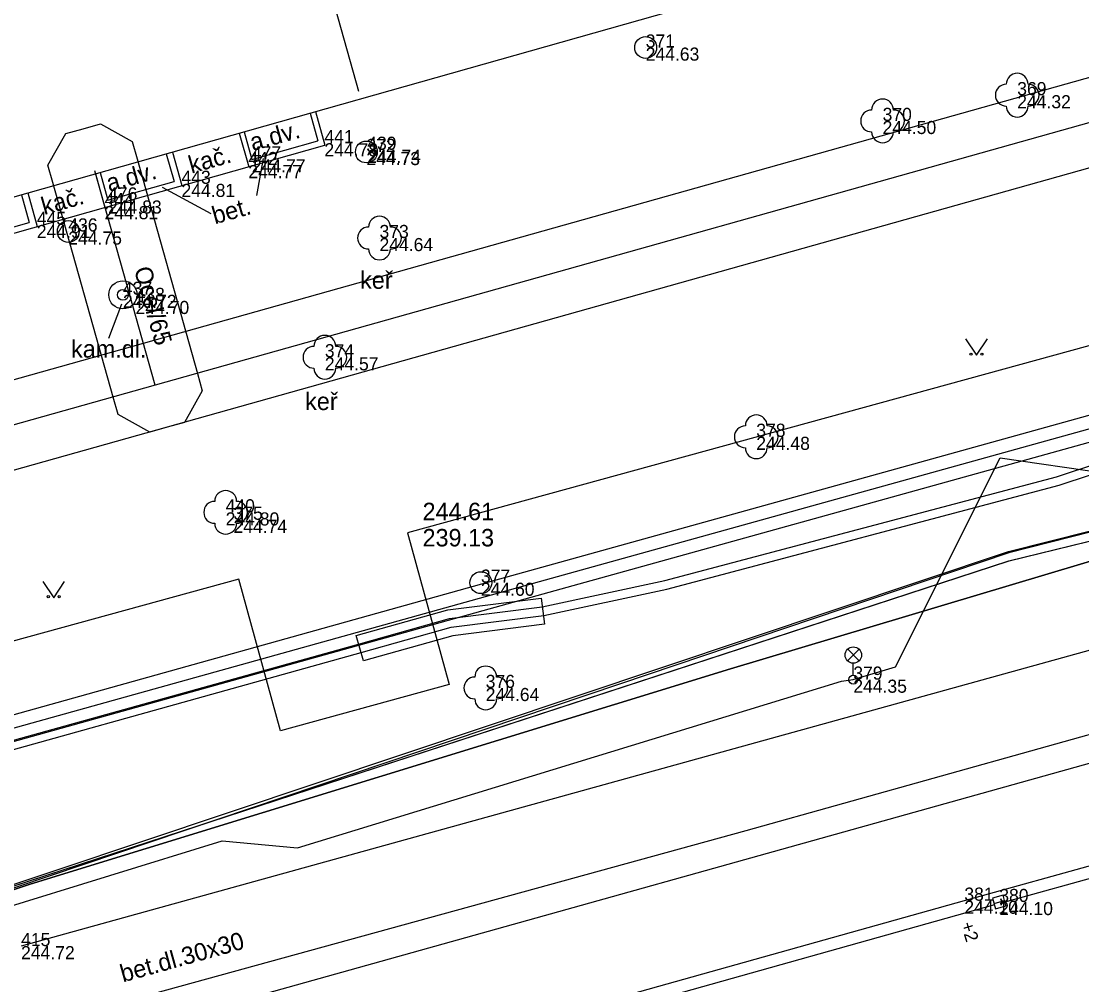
# Model space of a CAD drawing. Extents: x -599432 to -598680, y -1159407 to -1158632.
# Drawn here: x -599169.23 to -599144.96, y -1158932.91 to -1158910.85 of the extents above; entities that cross this region are included whole.
import ezdxf

# ---------------------------------------------------------------- set-up
doc = ezdxf.new("R2010")
doc.units = 0
for name, color, linetype in [('0004 VY - Body podrobné', 7, 'Continuous'), ('0005 VY - Body podrobné - čísla', 7, 'Continuous'), ('0006 VY - Body podrobné - výšky', 7, 'Continuous'), ('0007 ZA - Budova - zděná', 7, 'Continuous'), ('0027 ZA - Silnice_cesta zpevněná', 7, 'Continuous'), ('0028 ZA - Silnice - nájezd na chodník', 7, 'Continuous'), ('0030 ZA - Chodník', 7, 'Continuous'), ('0031 ZA - Ostatní rozhraní', 7, 'Continuous'), ('0032 TE - Popis povrchu', 7, 'Continuous'), ('0034 ZA - Kultury - značky', 7, 'Continuous'), ('0035 ZA - Strom - značka', 7, 'Continuous'), ('0036 TE - Strom - popis', 7, 'Continuous'), ('0073 TE - Výška obrubníků a zdí', 7, 'Continuous'), ('0075 ZA - BVK - kanalizace - buňky', 7, 'Continuous'), ('0092 ZA - RWE - plynovod - buňky', 7, 'Continuous'), ('0105 ZA - TSB - VO - buňky', 7, 'Continuous'), ('0116 PV - budova převzatá z mapy', 7, 'Continuous'), ('0201 PV - BVK - kanalizace - popis', 7, 'Continuous'), ('0202 PV - MUNI', 7, 'Continuous'), ('0206 PV - BVK - kanalizace - jednotná', 7, 'Continuous'), ('0211 PV - BVK - kanalizace - jednotná okraj', 7, 'Continuous'), ('0264 PV - TB - parovod mimo provoz', 7, 'Continuous'), ('0301 PV - RWE - popis', 7, 'Continuous'), ('0302 PV - RWE - NTL', 7, 'Continuous'), ('0303 PV - RWE - NTL přípojka', 7, 'Continuous'), ('0308 PV - RWE - ochranné pásmo', 7, 'Continuous'), ('0354 PV - EON - VN', 7, 'Continuous'), ('0359 PV - EON - sdělovací kabely', 7, 'Continuous'), ('0367 PV - EON - VN chránička', 7, 'Continuous'), ('0407 PV - TSB - kabelové vedení přibližný zákres', 7, 'Continuous'), ('0454 PV - O2 - kabel zaměřený', 7, 'Continuous'), ('0530 PV - T-mobile - optické kabely', 7, 'Continuous'), ('0652 PV - BKOM - kabely bez rozlišení', 7, 'Continuous'), ('0703 PV - DIAL TELECOM optický kabel', 7, 'Continuous'), ('0704 PV - ČD - kabely', 7, 'Continuous')]:
    doc.layers.add(name, color=color, linetype=linetype)

msp = doc.modelspace()

# ---------------------------------------------------------------- linework, layer by layer
at = {"layer": '0004 VY - Body podrobné'}
for p, q in [((-599154.94, -1158911.45), (-599154.94, -1158911.45)), ((-599146.44, -1158912.54), (-599146.44, -1158912.54)), ((-599149.52, -1158913.13), (-599149.52, -1158913.13)), ((-599162.29, -1158913.64), (-599162.29, -1158913.64)), ((-599163.95, -1158914.01), (-599163.95, -1158914.01)), ((-599161.33, -1158913.84), (-599161.33, -1158913.84)), ((-599161.31, -1158913.79), (-599161.31, -1158913.79)), ((-599164.03, -1158914.14), (-599164.03, -1158914.14)), ((-599165.56, -1158914.57), (-599165.56, -1158914.57)), ((-599167.24, -1158914.95), (-599167.24, -1158914.95)), ((-599167.32, -1158915.08), (-599167.32, -1158915.08)), ((-599168.87, -1158915.51), (-599168.87, -1158915.51)), ((-599168.15, -1158915.66), (-599168.15, -1158915.66)), ((-599161.03, -1158915.81), (-599161.03, -1158915.81)), ((-599166.9, -1158917.11), (-599166.9, -1158917.11)), ((-599166.61, -1158917.25), (-599166.61, -1158917.25)), ((-599162.28, -1158918.54), (-599162.28, -1158918.54)), ((-599152.41, -1158920.36), (-599152.41, -1158920.36)), ((-599164.55, -1158922.09), (-599164.55, -1158922.09)), ((-599164.37, -1158922.26), (-599164.37, -1158922.26)), ((-599158.71, -1158923.7), (-599158.71, -1158923.7)), ((-599158.6, -1158926.11), (-599158.6, -1158926.11)), ((-599150.19, -1158925.92), (-599150.19, -1158925.92)), ((-599147.65, -1158930.98), (-599147.65, -1158930.98)), ((-599146.85, -1158931.01), (-599146.85, -1158931.01))]:
    msp.add_line(p, q, dxfattribs=at)
at = {"layer": '0007 ZA - Budova - zděná'}
msp.add_line((-599202.3, -1158924.18), (-599142.02, -1158907.12), dxfattribs=at)
at = {"layer": '0027 ZA - Silnice_cesta zpevněná'}
msp.add_line((-599137.26, -1158925.73), (-599166.94, -1158934.03), dxfattribs=at)
at = {"layer": '0028 ZA - Silnice - nájezd na chodník'}
for p, q in [((-599088.5, -1158914.55), (-599147.65, -1158930.98)), ((-599147.65, -1158930.98), (-599167.27, -1158936.48))]:
    msp.add_line(p, q, dxfattribs=at)
at = {"layer": '0030 ZA - Chodník'}
msp.add_line((-599144.32, -1158925.12), (-599169.23, -1158932.02), dxfattribs=at)
at = {"layer": '0031 ZA - Ostatní rozhraní'}
for p, q in [((-599162.618, -1158912.95), (-599162.439, -1158913.585)), ((-599162.495, -1158912.915), (-599162.277, -1158913.685)), ((-599164.237, -1158913.408), (-599164.019, -1158914.178)), ((-599164.129, -1158913.377), (-599163.949, -1158914.012)), ((-599180.694, -1158918.897), (-599162.277, -1158913.685)), ((-599163.949, -1158914.012), (-599162.439, -1158913.585)), ((-599165.911, -1158913.881), (-599165.731, -1158914.516)), ((-599165.766, -1158913.841), (-599165.549, -1158914.61)), ((-599167.53, -1158914.34), (-599167.312, -1158915.109)), ((-599167.421, -1158914.309), (-599167.242, -1158914.944)), ((-599167.242, -1158914.944), (-599165.731, -1158914.516)), ((-599169.224, -1158914.819), (-599169.045, -1158915.454)), ((-599169.077, -1158914.778), (-599168.859, -1158915.547)), ((-599088.425, -1158914.82), (-599146.72, -1158931.012)), ((-599170.555, -1158915.882), (-599169.045, -1158915.454)), ((-599146.961, -1158931.078), (-599167.194, -1158936.75))]:
    msp.add_line(p, q, dxfattribs=at)
msp.add_circle((-599166.9, -1158917.11), 0.322, dxfattribs=at)
at = {"layer": '0032 TE - Popis povrchu'}
for p, q in [((-599163.835, -1158914.838), (-599163.682, -1158913.99)), ((-599164.884, -1158915.257), (-599165.997, -1158914.652)), ((-599167.223, -1158918.104), (-599166.928, -1158917.317))]:
    msp.add_line(p, q, dxfattribs=at)
at = {"layer": '0034 ZA - Kultury - značky'}
for points in [[(-599147.623, -1158918.118), (-599147.373, -1158918.493), (-599147.123, -1158918.118)], [(-599168.733, -1158923.67), (-599168.483, -1158924.045), (-599168.233, -1158923.67)]]:
    msp.add_lwpolyline(points, dxfattribs=at)
for centre in [(-599147.498, -1158918.468), (-599147.248, -1158918.468), (-599168.608, -1158924.02), (-599168.358, -1158924.02)]:
    msp.add_circle(centre, 0.025, dxfattribs=at)
at = {"layer": '0035 ZA - Strom - značka'}
for centre in [(-599146.44, -1158912.54), (-599149.52, -1158913.13), (-599161.03, -1158915.81), (-599162.28, -1158918.54), (-599152.41, -1158920.36), (-599164.55, -1158922.09), (-599158.6, -1158926.11)]:
    msp.add_circle(centre, 0.00025, dxfattribs=at)
for centre, start, end in [((-599146.44, -1158912.29), 0, 180), ((-599146.69, -1158912.54), 90, 270), ((-599146.19, -1158912.54), 270, 90), ((-599149.52, -1158912.88), 0, 180), ((-599146.44, -1158912.79), 180, 360), ((-599149.77, -1158913.13), 90, 270), ((-599149.27, -1158913.13), 270, 90), ((-599149.52, -1158913.38), 180, 360), ((-599161.03, -1158915.56), 0, 180), ((-599161.28, -1158915.81), 90, 270), ((-599160.78, -1158915.81), 270, 90), ((-599161.03, -1158916.06), 180, 360), ((-599162.28, -1158918.29), 0, 180), ((-599162.53, -1158918.54), 90, 270), ((-599162.03, -1158918.54), 270, 90), ((-599162.28, -1158918.79), 180, 360), ((-599152.41, -1158920.11), 0, 180), ((-599152.66, -1158920.36), 90, 270), ((-599152.16, -1158920.36), 270, 90), ((-599152.41, -1158920.61), 180, 360), ((-599164.55, -1158921.84), 0, 180), ((-599164.8, -1158922.09), 90, 270), ((-599164.3, -1158922.09), 270, 90), ((-599164.55, -1158922.34), 180, 360), ((-599158.6, -1158925.86), 0, 180), ((-599158.85, -1158926.11), 90, 270), ((-599158.35, -1158926.11), 270, 90), ((-599158.6, -1158926.36), 180, 360)]:
    msp.add_arc(centre, 0.25, start, end, dxfattribs=at)
at = {"layer": '0075 ZA - BVK - kanalizace - buňky'}
msp.add_line((-599146.971, -1158931.043), (-599146.729, -1158930.977), dxfattribs=at)
msp.add_lwpolyline([(-599146.938, -1158931.163), (-599146.697, -1158931.098), (-599146.762, -1158930.857), (-599147.003, -1158930.922)], close=True, dxfattribs=at)
for centre in [(-599154.94, -1158911.45), (-599161.33, -1158913.84), (-599168.15, -1158915.66), (-599158.71, -1158923.7)]:
    msp.add_circle(centre, 0.25, dxfattribs=at)
at = {"layer": '0092 ZA - RWE - plynovod - buňky'}
msp.add_circle((-599166.9, -1158917.11), 0.125, dxfattribs=at)
at = {"layer": '0105 ZA - TSB - VO - buňky'}
for p, q in [((-599150.322, -1158925.489), (-599150.058, -1158925.225)), ((-599150.054, -1158925.488), (-599150.318, -1158925.223)), ((-599150.19, -1158925.82), (-599150.19, -1158925.545))]:
    msp.add_line(p, q, dxfattribs=at)
for centre, radius in [((-599150.19, -1158925.357), 0.188), ((-599150.19, -1158925.92), 0.1)]:
    msp.add_circle(centre, radius, dxfattribs=at)
at = {"layer": '0116 PV - budova převzatá z mapy'}
msp.add_line((-599165.24, -1158899.13), (-599161.51, -1158912.45), dxfattribs=at)
at = {"layer": '0202 PV - MUNI'}
msp.add_lwpolyline([(-599255.365, -1158936.128), (-599252.9, -1158935.879), (-599249.514, -1158936.12), (-599229.166, -1158928.515), (-599221.329, -1158925.93), (-599220.289, -1158926.362), (-599218.079, -1158932.75), (-599214.197, -1158932.926), (-599209.818, -1158931.805), (-599201.617, -1158928.611), (-599200.477, -1158928.983), (-599199.188, -1158931.945), (-599199.148, -1158932.658), (-599198.604, -1158933.738), (-599197.027, -1158935.771), (-599194.361, -1158937.172), (-599193.665, -1158937.164), (-599183.138, -1158934.154), (-599174.357, -1158932.265), (-599146.637, -1158922.988), (-599125.848, -1158917.745)], dxfattribs=at)
at = {"layer": '0206 PV - BVK - kanalizace - jednotná'}
for p, q in [((-599158.607, -1158924.017), (-599091.321, -1158905.303)), ((-599214.704, -1158939.667), (-599158.607, -1158924.017))]:
    msp.add_line(p, q, dxfattribs=at)
at = {"layer": '0211 PV - BVK - kanalizace - jednotná okraj'}
for p, q in [((-599158.687, -1158923.728), (-599091.402, -1158905.014)), ((-599091.241, -1158905.592), (-599158.526, -1158924.307)), ((-599214.784, -1158939.378), (-599158.687, -1158923.729)), ((-599158.526, -1158924.306), (-599214.623, -1158939.956))]:
    msp.add_line(p, q, dxfattribs=at)
at = {"layer": '0264 PV - TB - parovod mimo provoz'}
msp.add_line((-599074.078, -1158898.846), (-599160.39, -1158922.56), dxfattribs=at)
for points in [[(-599164.247, -1158923.62), (-599240.684, -1158944.621), (-599259.43, -1158878.076)], [(-599160.39, -1158922.56), (-599159.436, -1158926.031), (-599163.293, -1158927.091), (-599164.247, -1158923.62)]]:
    msp.add_lwpolyline(points, dxfattribs=at)
at = {"layer": '0302 PV - RWE - NTL'}
msp.add_lwpolyline([(-599042.76, -1158885.49), (-599068.42, -1158892.17), (-599094.54, -1158899.36), (-599103.01, -1158901.75), (-599109.28, -1158903.4), (-599121.29, -1158906.57), (-599128.03, -1158908.44), (-599139.52, -1158911.687), (-599140.38, -1158911.93), (-599166.16, -1158919.18), (-599194.33, -1158927.1), (-599199.24, -1158928.46), (-599225.65, -1158935.9)], dxfattribs=at)
at = {"layer": '0303 PV - RWE - NTL přípojka'}
msp.add_lwpolyline([(-599166.16, -1158919.18), (-599167.54, -1158914.27)], dxfattribs=at)
at = {"layer": '0308 PV - RWE - ochranné pásmo'}
msp.add_lwpolyline([(-599140.109, -1158912.892), (-599165.889, -1158920.143), (-599194.061, -1158928.063), (-599198.971, -1158929.423), (-599225.379, -1158936.863), (-599225.777, -1158936.975), (-599226.5, -1158936.57), (-599226.613, -1158936.171), (-599226.725, -1158935.773), (-599226.32, -1158935.05), (-599225.921, -1158934.937), (-599199.509, -1158927.497), (-599194.599, -1158926.137), (-599166.431, -1158918.217), (-599140.651, -1158910.968)], dxfattribs=at)
msp.add_lwpolyline([(-599167.011, -1158919.849), (-599167.123, -1158919.451), (-599168.503, -1158914.541), (-599168.615, -1158914.142), (-599168.209, -1158913.419), (-599167.811, -1158913.307), (-599167.412, -1158913.195), (-599166.689, -1158913.601), (-599166.577, -1158913.999), (-599165.197, -1158918.909), (-599165.085, -1158919.308), (-599165.491, -1158920.031), (-599165.889, -1158920.143), (-599166.288, -1158920.255)], close=True, dxfattribs=at)
at = {"layer": '0354 PV - EON - VN'}
for points in [[(-599194.109, -1158934.002), (-599187.194, -1158932.813), (-599181.87, -1158931.105), (-599173.269, -1158928.384), (-599161.507, -1158925.104), (-599159.43, -1158924.522), (-599157.307, -1158924.251), (-599154.503, -1158923.653), (-599145.539, -1158921.274), (-599140.537, -1158919.624)], [(-599194.071, -1158934.198), (-599187.146, -1158933.007), (-599181.81, -1158931.295), (-599173.211, -1158928.576), (-599161.453, -1158925.296), (-599159.39, -1158924.718), (-599157.273, -1158924.449), (-599154.457, -1158923.847), (-599145.481, -1158921.466), (-599140.483, -1158919.816)]]:
    msp.add_lwpolyline(points, dxfattribs=at)
at = {"layer": '0359 PV - EON - sdělovací kabely'}
msp.add_lwpolyline([(-599279.16, -1158962.47), (-599254.08, -1158955.38), (-599253.49, -1158954.94), (-599253.3, -1158954.3), (-599252.93, -1158950.8), (-599250.35, -1158946.57), (-599249.33, -1158946.19), (-599247.7, -1158945.87), (-599212.14, -1158935.06), (-599209.49, -1158932.25), (-599207.11, -1158930.84), (-599200.83, -1158928.66), (-599200.36, -1158929.03), (-599198.47, -1158933.96), (-599197.14, -1158935.93), (-599194.75, -1158937.1), (-599192.69, -1158937.18), (-599181.15, -1158933.71), (-599175.84, -1158932.87), (-599169.02, -1158930.6), (-599153, -1158925.67), (-599136.91, -1158920.86)], dxfattribs=at)
msp.add_lwpolyline([(-599279.16, -1158962.47), (-599254.08, -1158955.38), (-599253.49, -1158954.94), (-599253.3, -1158954.3), (-599252.93, -1158950.8), (-599250.35, -1158946.57), (-599249.33, -1158946.19), (-599247.7, -1158945.87), (-599212.14, -1158935.06), (-599209.49, -1158932.25), (-599207.11, -1158930.84), (-599200.83, -1158928.66), (-599200.36, -1158929.03), (-599198.47, -1158933.96), (-599197.14, -1158935.93), (-599194.75, -1158937.1), (-599192.69, -1158937.18), (-599181.15, -1158933.71), (-599175.84, -1158932.87), (-599169.02, -1158930.6), (-599153, -1158925.67), (-599136.91, -1158920.86)], dxfattribs=at)
at = {"layer": '0367 PV - EON - VN chránička'}
for p, q in [((-599159.47, -1158924.325), (-599157.328, -1158924.052)), ((-599157.328, -1158924.052), (-599157.252, -1158924.648)), ((-599161.561, -1158924.911), (-599159.47, -1158924.325)), ((-599157.252, -1158924.648), (-599159.35, -1158924.915)), ((-599161.399, -1158925.489), (-599161.561, -1158924.911)), ((-599159.35, -1158924.915), (-599161.399, -1158925.489))]:
    msp.add_line(p, q, dxfattribs=at)
at = {"layer": '0407 PV - TSB - kabelové vedení přibližný zákres'}
for p, q in [((-599149.227, -1158925.625), (-599146.829, -1158920.84)), ((-599146.829, -1158920.84), (-599143.039, -1158921.389)), ((-599150.19, -1158925.92), (-599149.227, -1158925.625)), ((-599154.79, -1158927.283), (-599150.459, -1158925.955)), ((-599150.459, -1158925.955), (-599150.19, -1158925.92)), ((-599162.905, -1158929.771), (-599154.79, -1158927.283)), ((-599175.063, -1158932.821), (-599164.629, -1158929.611)), ((-599164.629, -1158929.611), (-599162.905, -1158929.771))]:
    msp.add_line(p, q, dxfattribs=at)
at = {"layer": '0454 PV - O2 - kabel zaměřený'}
msp.add_lwpolyline([(-599214.12, -1158932.98), (-599209.84, -1158931.94), (-599204.25, -1158929.61), (-599201.63, -1158928.74), (-599200.52, -1158929.11), (-599199.22, -1158932.37), (-599199.21, -1158932.71), (-599198.67, -1158933.82), (-599197.15, -1158935.83), (-599194.3, -1158937.23), (-599193.72, -1158937.24), (-599183.02, -1158934.19), (-599174.44, -1158932.29), (-599146.63, -1158923.2), (-599137.96, -1158921.08)], dxfattribs=at)
at = {"layer": '0530 PV - T-mobile - optické kabely'}
for points in [[(-599153, -1158925.67), (-599136.91, -1158920.859)], [(-599146.626, -1158923.197), (-599137.957, -1158921.076)], [(-599174.436, -1158932.287), (-599146.626, -1158923.197)], [(-599169.02, -1158930.599), (-599153, -1158925.67)], [(-599175.84, -1158932.869), (-599169.02, -1158930.599)]]:
    msp.add_lwpolyline(points, dxfattribs=at)
at = {"layer": '0652 PV - BKOM - kabely bez rozlišení'}
msp.add_lwpolyline([(-599194.67, -1158942.89), (-599194.47, -1158942.81), (-599193.85, -1158942.64), (-599178.5, -1158938.24), (-599178, -1158938.49), (-599168.91, -1158935.86), (-599168.03, -1158933.61), (-599152.64, -1158929.37), (-599137, -1158924.99)], dxfattribs=at)
at = {"layer": '0703 PV - DIAL TELECOM optický kabel'}
msp.add_lwpolyline([(-599061.55, -1158893.87), (-599061.24, -1158895.32), (-599061.95, -1158898.88), (-599063.86, -1158900.66), (-599074.72, -1158903.34), (-599088.3, -1158908.08), (-599104.33, -1158911.91), (-599119.51, -1158916.31), (-599136.91, -1158920.86), (-599153, -1158925.67), (-599169.02, -1158930.6), (-599175.84, -1158932.87), (-599181.15, -1158933.71), (-599192.69, -1158937.18), (-599194.75, -1158937.1), (-599197.14, -1158935.93), (-599198.47, -1158933.96), (-599200.36, -1158929.03), (-599200.83, -1158928.66), (-599207.11, -1158930.84)], dxfattribs=at)
at = {"layer": '0704 PV - ČD - kabely'}
msp.add_lwpolyline([(-599114.022, -1158914.733), (-599146.63, -1158923.02), (-599155.536, -1158926.021), (-599174.713, -1158932.481), (-599184.127, -1158934.514), (-599194.001, -1158937.403), (-599194.747, -1158937.133), (-599197.224, -1158935.816), (-599199.288, -1158932.926), (-599199.494, -1158931.958), (-599200.756, -1158929.108), (-599201.883, -1158928.791), (-599209.995, -1158931.998), (-599214.441, -1158933.077), (-599217.743, -1158932.664), (-599219.108, -1158931.045), (-599220.314, -1158926.664), (-599221.203, -1158926.41), (-599249.842, -1158936.887), (-599252.604, -1158936.443), (-599255.248, -1158936.617)], dxfattribs=at)

# ---------------------------------------------------------------- texts
at = {"layer": '0005 VY - Body podrobné - čísla'}
for s, p in [('371', (-599154.94, -1158911.45)), ('369', (-599146.44, -1158912.54)), ('370', (-599149.52, -1158913.13)), ('441', (-599162.29, -1158913.64)), ('439', (-599161.31, -1158913.79)), ('477', (-599163.95, -1158914.01)), ('372', (-599161.33, -1158913.84)), ('442', (-599164.03, -1158914.14)), ('443', (-599165.56, -1158914.57)), ('476', (-599167.24, -1158914.95)), ('444', (-599167.32, -1158915.08)), ('445', (-599168.87, -1158915.51)), ('436', (-599168.15, -1158915.66)), ('373', (-599161.03, -1158915.81)), ('437', (-599166.9, -1158917.11)), ('438', (-599166.61, -1158917.25)), ('374', (-599162.28, -1158918.54)), ('378', (-599152.41, -1158920.36)), ('440', (-599164.55, -1158922.09)), ('375', (-599164.37, -1158922.26)), ('377', (-599158.71, -1158923.7)), ('379', (-599150.19, -1158925.92)), ('376', (-599158.6, -1158926.11)), ('381', (-599147.65, -1158930.98)), ('380', (-599146.85, -1158931.01)), ('415', (-599169.23, -1158932.02))]:
    msp.add_text(s, height=0.3, dxfattribs=at).set_placement(p)
at = {"layer": '0006 VY - Body podrobné - výšky'}
for s, p in [('244.63', (-599154.94, -1158911.75)), ('244.32', (-599146.44, -1158912.84)), ('244.50', (-599149.52, -1158913.43)), ('244.78', (-599162.29, -1158913.94)), ('244.77', (-599163.95, -1158914.31)), ('244.73', (-599161.33, -1158914.14)), ('244.74', (-599161.31, -1158914.09)), ('244.77', (-599164.03, -1158914.44)), ('244.81', (-599165.56, -1158914.87)), ('244.83', (-599167.24, -1158915.25)), ('244.81', (-599167.32, -1158915.38)), ('244.91', (-599168.87, -1158915.81)), ('244.75', (-599168.15, -1158915.96)), ('244.64', (-599161.03, -1158916.11)), ('244.72', (-599166.9, -1158917.41)), ('244.70', (-599166.61, -1158917.55)), ('244.57', (-599162.28, -1158918.84)), ('244.48', (-599152.41, -1158920.66)), ('244.80', (-599164.55, -1158922.39)), ('244.74', (-599164.37, -1158922.56)), ('244.60', (-599158.71, -1158924)), ('244.64', (-599158.6, -1158926.41)), ('244.35', (-599150.19, -1158926.22)), ('244.10', (-599147.65, -1158931.28)), ('244.10', (-599146.85, -1158931.31)), ('244.72', (-599169.23, -1158932.32))]:
    msp.add_text(s, height=0.3, dxfattribs=at).set_placement(p)
at = {"layer": '0032 TE - Popis povrchu'}
for s, rotation, p in [('a.dv.', 15.6438, (-599163.931, -1158913.82)), ('kač.', 15.8022, (-599165.333, -1158914.337)), ('a.dv.', 15.6438, (-599167.215, -1158914.756)), ('kač.', 15.8022, (-599168.702, -1158915.285)), ('bet.', 15.8022, (-599164.796, -1158915.497)), ('bet.dl.30x30', 15.5705, (-599166.899, -1158932.852))]:
    msp.add_text(s, height=0.4, rotation=rotation, dxfattribs=at).set_placement(p)
msp.add_text('kam.dl.', height=0.4, dxfattribs=at).set_placement((-599168.087, -1158918.548))
at = {"layer": '0036 TE - Strom - popis'}
for p in [(-599161.473, -1158916.973), (-599162.731, -1158919.748)]:
    msp.add_text('keř', height=0.4, dxfattribs=at).set_placement(p)
at = {"layer": '0073 TE - Výška obrubníků a zdí'}
msp.add_text('+2', height=0.3, rotation=286.775, dxfattribs=at).set_placement((-599147.734, -1158931.512))
at = {"layer": '0201 PV - BVK - kanalizace - popis'}
for s, p in [('244.61', (-599160.045, -1158922.27)), ('239.13', (-599160.045, -1158922.87))]:
    msp.add_text(s, height=0.4, dxfattribs=at).set_placement(p)
at = {"layer": '0301 PV - RWE - popis'}
msp.add_text('Ocel/65', height=0.4, rotation=285.6985, dxfattribs=at).set_placement((-599166.65, -1158916.525))

doc.saveas('drawing.dxf')
